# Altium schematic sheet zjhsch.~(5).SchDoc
size A4
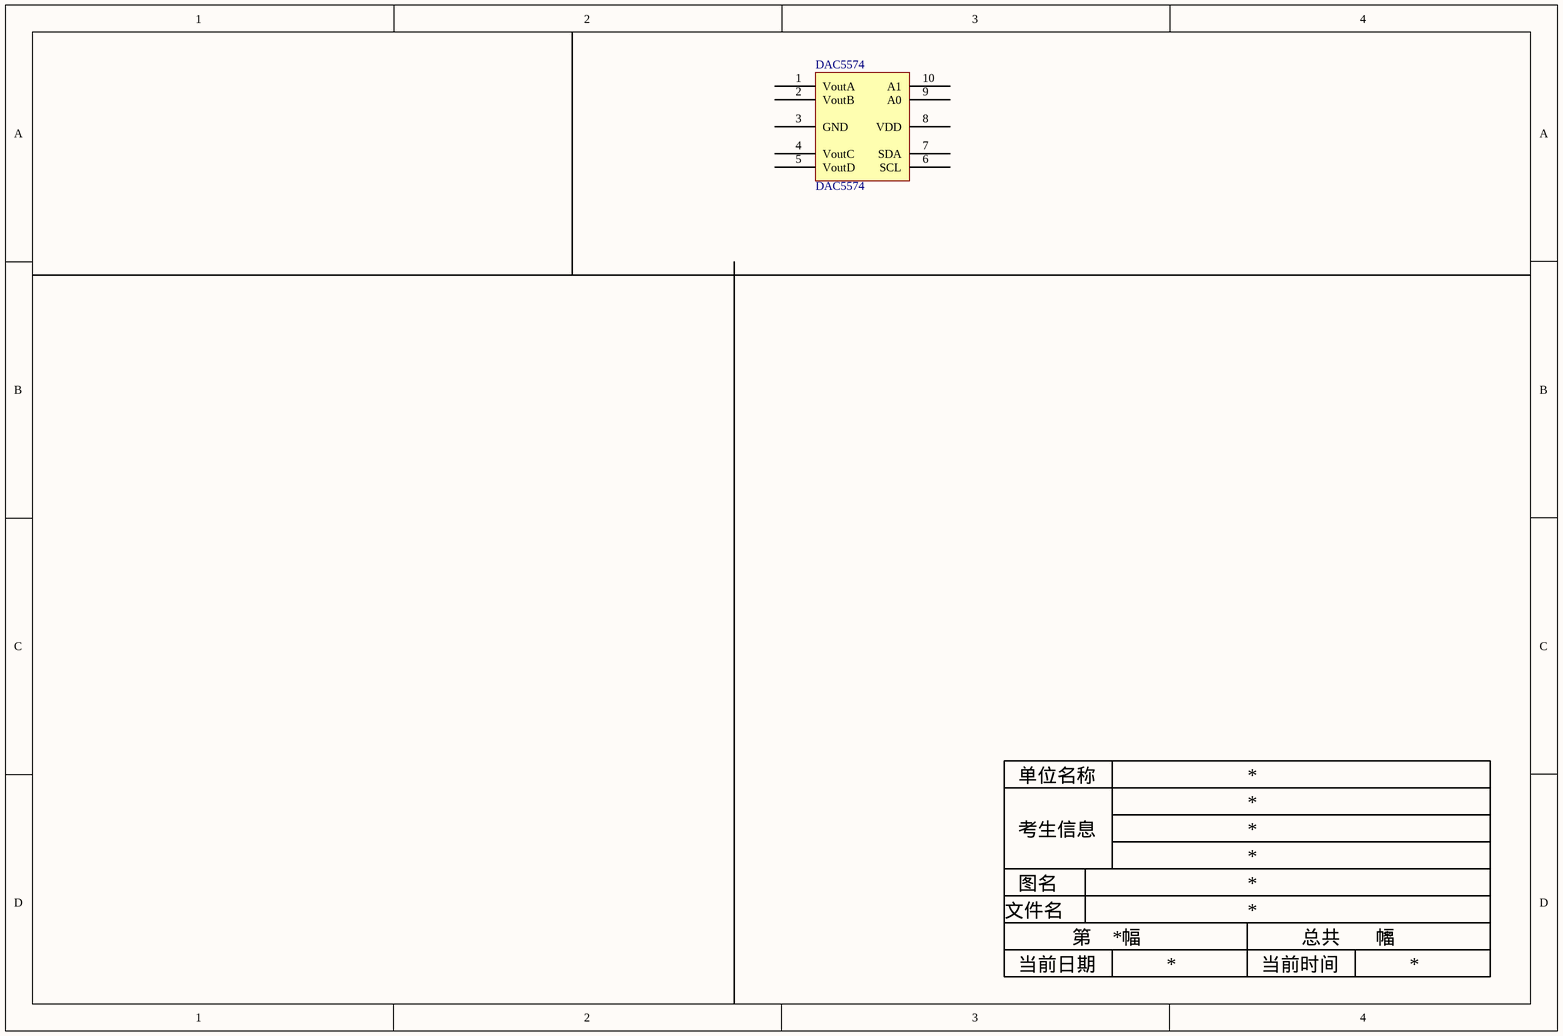
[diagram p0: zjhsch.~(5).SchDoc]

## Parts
DAC5574  DAC5574

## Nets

Not connected (* = marked no-connect by the designer): DAC5574 1(VoutA) 2(VoutB) 3(GND) 4(VoutC) 5(VoutD) 6(SCL) 7(SDA) 8(VDD) 9(A0) 10(A1)

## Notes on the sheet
- 单位名称
- 考生信息
- 文件名
- 图名
- 当前日期
- 第      幅
- 当前时间
- 总共       幅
